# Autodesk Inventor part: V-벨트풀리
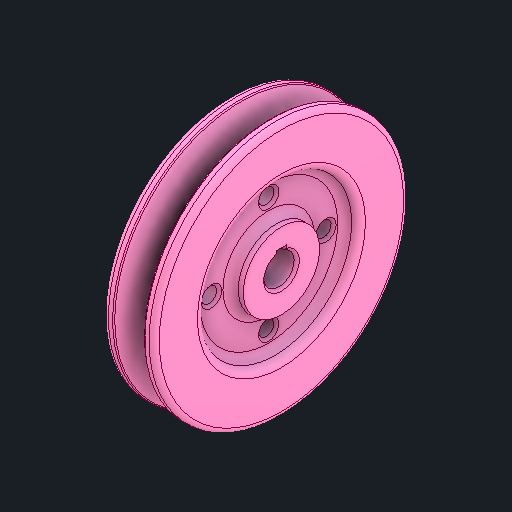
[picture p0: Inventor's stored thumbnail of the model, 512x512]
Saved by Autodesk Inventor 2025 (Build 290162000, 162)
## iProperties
Created: 2025-08
Part Number: V-벨트풀리
Material: 강철, 연강
Document SubType Name: Modeling
Designer: infra006
Density: 7.86 g/cm^3
Appearance: 기본값
Author: jhkim
Sending System: Autodesk Inventor 2026
Preprocessor: ST-DEVELOPER v20.1
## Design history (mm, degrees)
feature "솔리드1"
node "솔리드2"
